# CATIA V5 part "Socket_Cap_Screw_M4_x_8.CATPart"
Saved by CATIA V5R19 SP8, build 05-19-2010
Part number: Socket Cap Screw M4 x 8
Definition: 70552
Material "Chrome": density 7190 kg/m3, Young's modulus 7e+10 Pa, Poisson ratio 0.3, thermal expansion 6.2e-06 1/K
Bounding box of the stored display mesh (mm): x -4.195 to 4.195, y -4.199 to 4.199, z -2.918 to 8
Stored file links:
  D:\Documents\1_Travail\1 - ac-limoges.fr\ac-limoges.fr\Emmanuel Maynard - STI2D_Turgot\1 - IT-I2D\Activités_IT_Première\IT_3_Abris_bus\Maquettes numériques\Abribus_eleve\Socket_Cap_Screw_M4_x_8.CATPart
  C:\Program Files\Dassault Systemes\B19\win_b64\startup\materials\French\Catalog.CATMaterial
  C:\Program Files\Dassault Systemes\B19\win_b64\reffiles\standard\MetricThickPitch.txt
  D:\Documents\1_Travail\2- 2I2D\6 -  Ressources ITEC\Ressources Techniques\0-Maquettes numériques_Composants\Catalogue_Makeblock\Catalog_Makeblock\08_Visserie\Table Vis bombeesM4.xls
  D:\Documents\1_Travail\2- 2I2D\6 -  Ressources ITEC\Ressources Techniques\0-Maquettes numériques_Composants\Catalogue_Makeblock\Catalog_Makeblock\08_Visserie\Table Vis bombeesM4.txt
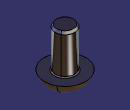
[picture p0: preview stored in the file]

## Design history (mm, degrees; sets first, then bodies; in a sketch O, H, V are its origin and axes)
Parameters
  Longueur = 8 mm
  `Longueur filetée` = 7 mm
  `Désignation` = "Socket Cap Screw M4 x 8"
  `Référence` = "70552"
AxisSystem1: origin (0, 0, 0), X (1, 0, 0), Y (0, 1, 0), Z (0, 0, 1)
Body1 (main body), material "Chrome"
  Sketch1 on ZX plane of AxisSystem1, origin (0, 0, 0), H (0, 0, 1), V (1, 0, 0)
    point P1 (0, 4.2)
    line L1 (0, 4.2) -> (0, 2)
    line L2 (0, 2) -> (8, 2)
    line L3 (8, 2) -> (8, 0)
    point P4 (8, 0)
    point P5 (1.2952, 0)
    axis line L4 (-59.0265, 0) -> (107.0959, 0)
    point P6 (-59.0265, 0)
    point P8 (-3.1, 0)
    arc A1 centre (1.2952, 0) radius 4.3952 from (0, 4.2) to (-3.1, 0) ccw
    distance L2 L4 = 2
    distance L3 L1 = 8 {= Longueur}
    distance P8 L1 = 3.1
    distance P1 L4 = 4.2
    coincidence: P1 V, P4 H, P5 H, P6 H, L4 P8
    vertical: L1 V, L3 V
    horizontal: L2 H, L4 H
  Shaft1: profile Sketch1, axis Sketch1.L4, angle 360
  Fillet1: radius 0.2, on edge [face of Shaft1 from Sketch1.L1 | face of Shaft1 from Sketch1.L2]
  Body2
    Sketch2 on XY plane of AxisSystem1, origin (0, 0, 0), H (1, 0, 0), V (0, 1, 0)
      point P1 (0.7217, 1.25)
      point P2 (-0.7217, 1.25)
      point P3 (-1.4434, 0)
      point P4 (-0.7217, -1.25)
      point P5 (0.7217, -1.25)
      point P6 (1.4434, 0)
      point P7 (0, 1.25)
      line L1 (0.7217, 1.25) -> (-0.7217, 1.25)
      line L2 (-0.7217, 1.25) -> (-1.4434, 0)
      line L3 (-1.4434, 0) -> (-0.7217, -1.25)
      line L4 (-0.7217, -1.25) -> (0.7217, -1.25)
      line L5 (0.7217, -1.25) -> (1.4434, 0)
      line L6 (1.4434, 0) -> (0.7217, 1.25)
      construction line L7 (0, 0) -> (0, 1.25)
      construction circle A1 centre (0, 0) radius 1.4434
      construction arc A2 centre (0.7217, -1.25) radius 1.4434 from (-0.7217, -1.25) to (1.4434, 0) cw
      construction arc A3 centre (-0.7217, 1.25) radius 1.4434 from (-1.4434, 0) to (0.7217, 1.25) ccw
      distance L5 L2 = 2.5
      vertical: L7 V
      coincidence: A1 P1, A1 P2, A1 P3, A1 P4, A1 P5, A1 P6, A2 O, A3 O
      midpoint: P7 L1
      parallelism: L1 L4
    Pad1: profile Sketch2, direction (0, 0, -1), length 5
    Chamfer1: length 1.2, angle 30, on start face of Pad1
  Remove1: tool Body2
  Thread1: "M4", diameter 4, depth 7 {= `Longueur filetée`}, pitch 0.7, on face of Shaft1 from Sketch1.L2, from face of Shaft1 from Sketch1.L3
  Chamfer2: length 0.5, angle 30, on edge [face of Shaft1 from Sketch1.L2 | face of Shaft1 from Sketch1.L3]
